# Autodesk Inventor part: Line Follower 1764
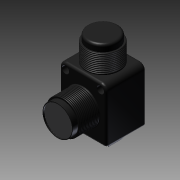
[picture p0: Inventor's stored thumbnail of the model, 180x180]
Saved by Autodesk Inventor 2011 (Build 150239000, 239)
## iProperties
Created: 2011-02
Part Number: Line Follower 1764
Document SubType Name: Modeling
Designer: dfranz
Density: 1 g/cm^3
Author: dfranz
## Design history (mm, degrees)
sketch "Sketch1"
  geometry: L1 (0, 0)-(-24.765, 0); L2 (-24.765, 0)-(-24.765, 27.305); L3 (-24.765, 27.305)-(0, 27.305); L4 (0, 27.305)-(0, 0)
  constraints: 8 end point, 2 parallel, 1 horizontal, 1 perpendicular
  dimensions: "d0" = 24.765 distance of L2.end L3.end; "d1" = 27.305 distance of L1.end L2.end
extrude "Extrusion1" new body sketch "Sketch1" distance "d2" = 20.955; taper "d3" = 0 deg
fillet "Fillet1" dims "d4" = 3.175
sketch "Sketch2"
  geometry: C1 r 7.938 at (-12.383, 12.065)
  constraints: 1 centre point
  dimensions: "d5" = 15.875 diameter of C1
extrude "Extrusion2" join sketch "Sketch2" distance "d6" = 13.335; taper "d7" = 0 deg
sketch "Sketch3"
  geometry: C1 r 7.937 at (-12.383, 12.065) reference; C2 r 8.89 at (-12.383, 12.065)
  constraints: 1 centre point, 1 coincident
  dimensions: "d8" = 17.78 diameter of C2
extrude "Extrusion3" join sketch "Sketch3" distance "d9" = 0.635; taper "d10" = 0 deg
pattern_linear "Rectangular Pattern1" dims "d13" = 0.8255
pattern_linear "Rectangular Pattern2" dims "d17" = 0.8255
fillet "Fillet3" dims "d18" = 0.3175
sketch "Sketch4"
  geometry: C1 r 1.905 at (-21.59, 24.13); C2 r 1.905 at (-3.175, 24.13); A1 r 3.175 centre (-21.59, 24.13) between (-21.59, 27.305) and (-24.765, 24.13) reference; A2 r 3.175 centre (-3.175, 24.13) between (0, 24.13) and (-3.175, 27.305) reference
  constraints: 2 centre point, 2 coincident
  dimensions: "d19" = 3.81 diameter of C1; "d20" = 3.81 diameter of C2
extrude "Extrusion4" cut sketch "Sketch4" stored distance "d21" = 0.635; taper "d22" = 0 deg
sketch "Sketch6"
  geometry: C1 r 7.938 at (9.208, -10.477); 1 further point
  constraints: 1 centre point
  dimensions: "d26" = 15.875 diameter of C1
extrude "Extrusion6" join sketch "Sketch6" distance "d27" = 13.335; taper "d28" = 0 deg
sketch "Sketch7"
  geometry: C1 r 7.937 at (9.208, -10.477) reference; C2 r 8.89 at (9.208, -10.477); 1 further point
  constraints: 1 centre point, 1 coincident
  dimensions: "d29" = 17.78 diameter of C2
extrude "Extrusion7" join sketch "Sketch7" distance "d30" = 0.635; taper "d31" = 0 deg
pattern_linear "Rectangular Pattern3" dims "d34" = 0.8255
fillet "Fillet4" dims "d35" = 0.3175, "d36" = 1.27
sketch "Sketch8"
  geometry: L1 (22.225, 20.955)-(0, 20.955) reference; L2 (-1.27, 1.27)-(-1.27, 19.685) reference; L3 (22.225, 0)-(0, 0) reference; L4 (23.495, 1.27)-(23.495, 19.685) reference; L5 (-1.206, 1.27)-(-1.206, 19.685); L6 (0, 20.891)-(22.225, 20.892); L7 (23.432, 19.685)-(23.432, 1.27); L8 (22.225, 0.063)-(0, 0.063); A1 r 1.27 centre (22.225, 19.685) between (23.495, 19.685) and (22.225, 20.955) reference; A2 r 1.27 centre (0, 19.685) between (0, 20.955) and (-1.27, 19.685) reference; A3 r 1.27 centre (0, 1.27) between (-1.27, 1.27) and (0, 0) reference; A4 r 1.27 centre (22.225, 1.27) between (22.225, 0) and (23.495, 1.27) reference; A5 r 1.207 centre (0, 1.27) between (-1.206, 1.27) and (0, 0.063); A6 r 1.207 centre (0, 19.685) between (0, 20.891) and (-1.206, 19.685); A7 r 1.207 centre (22.225, 19.685) between (23.432, 19.685) and (22.225, 20.892); A8 r 1.207 centre (22.225, 1.27) between (22.225, 0.063) and (23.432, 1.27); 1 further point
  constraints: 8 end point, 8 point on circle, 4 centre point, 7 other
  dimensions: "d39" = 0.0635 distance between parallel lines of L3 L8
extrude "Extrusion8" join sketch "Sketch8" distance "d37" = 0.635; taper "d38" = 0 deg
sketch "Sketch9"
  geometry: C1 r 7.937 at (0, 0) reference; C2 r 7.62 at (0, 0); 1 further point
  constraints: 1 centre point, 1 coincident
  dimensions: "d40" = 15.24 diameter of C2
extrude "Extrusion9" cut sketch "Sketch9" distance "d41" = 0.635; taper "d42" = 0 deg
sketch "Sketch10"
  geometry: L1 (-1.206, 1.27)-(-1.206, 19.685) reference; L2 (23.432, 19.685)-(23.432, 1.27) reference; L3 (0, 20.891)-(22.225, 20.892) reference; L4 (22.162, 10.097)-(0.064, 10.096); L5 (0.064, 10.096)-(0.064, 18.351); L6 (0.064, 18.351)-(22.162, 18.352); L7 (22.162, 18.352)-(22.162, 10.097); L8 (15.177, 10.096)-(7.049, 10.096); L9 (7.049, 10.096)-(7.049, 7.556); L10 (7.049, 7.556)-(15.177, 7.556); L11 (15.177, 7.556)-(15.177, 10.096); A1 r 4.064 centre (11.113, 7.556) between (7.049, 7.556) and (15.177, 7.556); 1 further point
  constraints: 16 end point, 4 parallel, 2 horizontal, 2 perpendicular, 2 point on circle, 2 tangent, 1 centre point, 1 point on line
  dimensions: "d43" = 8.255 distance of L4.end L5.end; "d44" = 2.54 distance between parallel lines of L6 L3; "d45" = 2.54 distance of L10.end L8.start; "d46" = 1.27 distance between parallel lines of L2 L7; "d47" = 1.27 distance between parallel lines of L1 L5; "d48" = 8.255 distance between parallel lines of L2 L11; "d49" = 8.255 distance between parallel lines of L1 L9
extrude "Extrusion10" join sketch "Sketch10" distance "d50" = 3.81; taper "d51" = 0 deg
fillet "Fillet5" dims "d52" = 0.381, "d53" = 3.81
sketch "Sketch11"
  geometry: C1 r 3.175 at (11.113, 7.556); A1 r 3.683 centre (11.113, 7.556) between (7.43, 7.556) and (14.796, 7.556) reference; 1 further point
  constraints: 1 centre point, 1 coincident
  dimensions: "d54" = 6.35 diameter of C1
extrude "Extrusion11" join sketch "Sketch11" distance "d55" = 1.27; taper "d56" = 0 deg
fillet "Fillet6" dims "d57" = 1.27
body "Solid1"
